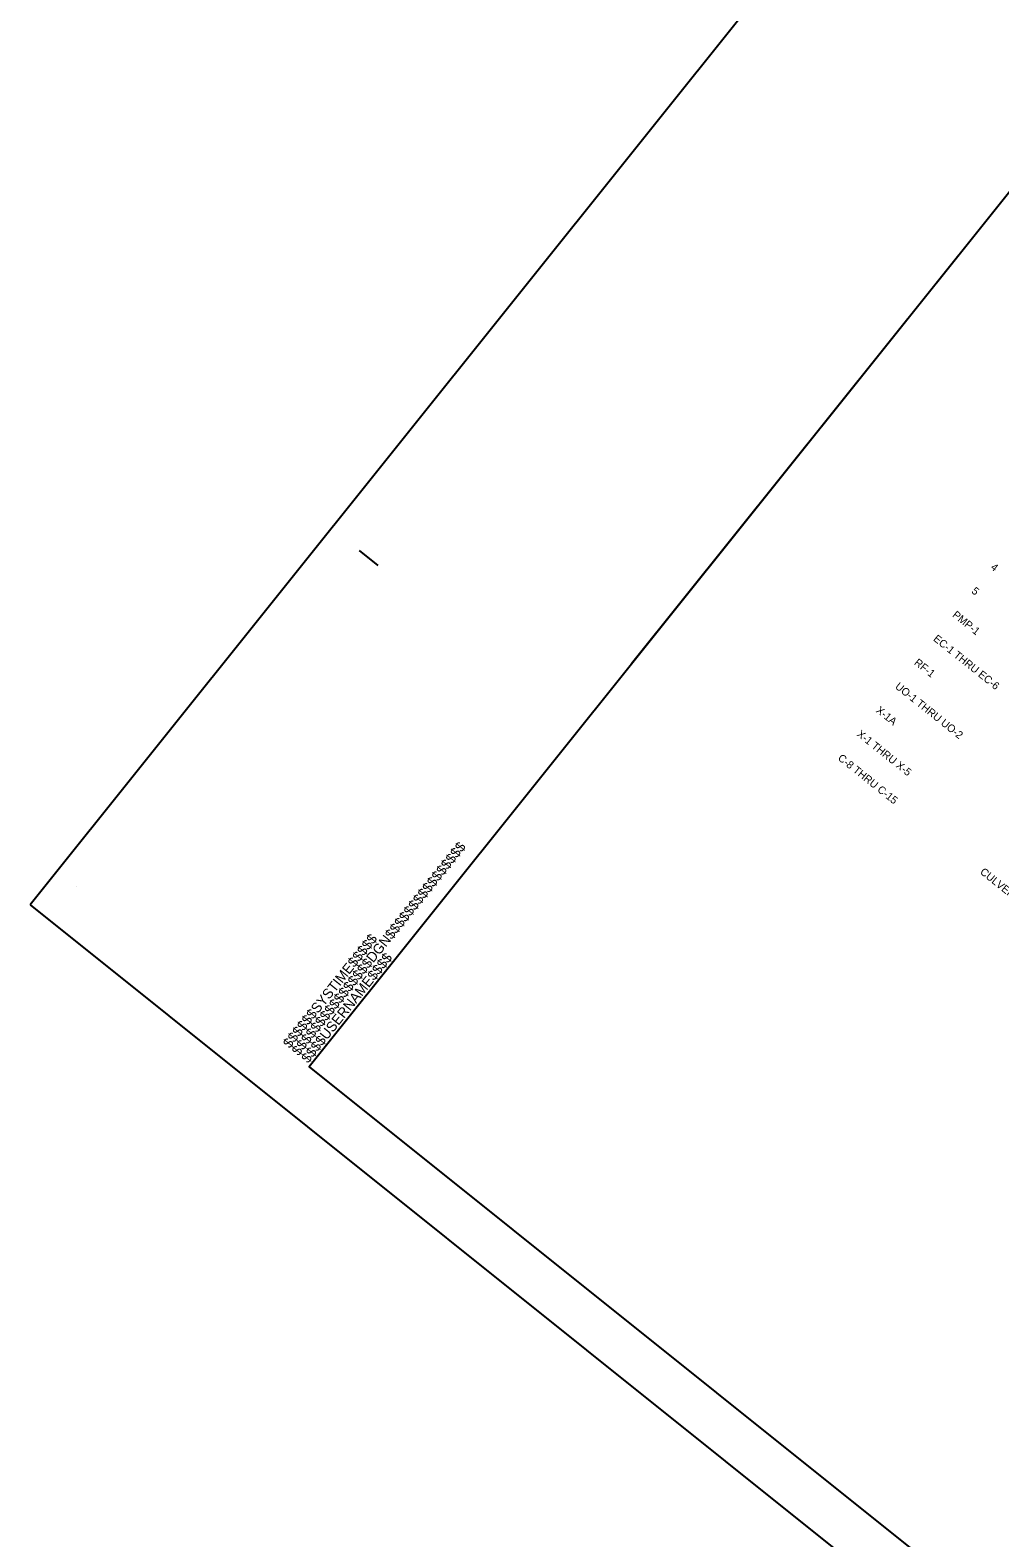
# Model space of a CAD drawing. Extents: x 1730256 to 1738218, y 910410 to 917906.
# Drawn here: x 1730256 to 1730764, y 911131 to 911921 of the extents above; entities that cross this region are included whole.
import ezdxf

# ---------------------------------------------------------------- set-up
doc = ezdxf.new("R2010")
doc.units = 0
for name, color, linetype in [('Old_Level_1', 7, 'Continuous'), ('Old_Level_18', 7, 'Continuous'), ('Old_Level_40', 7, 'Continuous'), ('Old_Level_41', 7, 'Continuous'), ('Old_Level_50', 7, 'Continuous'), ('Old_Level_51', 7, 'Continuous'), ('Old_Level_52', 7, 'Continuous')]:
    doc.layers.add(name, color=color, linetype=linetype)

msp = doc.modelspace()

# ---------------------------------------------------------------- linework, layer by layer
at = {"layer": 'Old_Level_1'}
msp.add_line((1731058.58, 912197.51), (1730571.35, 911588.71), dxfattribs=at)
at = {"layer": 'Old_Level_18'}
msp.add_line((1730402.49, 911377.72), (1730402.49, 911377.72), dxfattribs=at)
msp.add_lwpolyline([(1732229.7, 911260.24), (1731058.58, 912197.51), (1730402.49, 911377.72), (1731573.62, 910440.45)], close=True, dxfattribs=at)
at = {"layer": 'Old_Level_40'}
msp.add_line((1730402.49, 911377.72), (1730402.49, 911377.72), dxfattribs=at)
msp.add_line((1730402.49, 911377.72), (1730402.49, 911377.72), dxfattribs=at)
msp.add_line((1730402.49, 911377.72), (1730402.49, 911377.72), dxfattribs=at)
msp.add_line((1730402.49, 911377.72), (1730402.49, 911377.72), dxfattribs=at)
at = {"layer": 'Old_Level_41'}
msp.add_line((1730428.7, 911648.13), (1730438.46, 911640.32), dxfattribs=at)
msp.add_lwpolyline([(1730509.85, 911291.8), (1730509.85, 911291.8)], dxfattribs=at)
at = {"layer": 'Old_Level_50'}
msp.add_line((1730256.49, 911462.55), (1730256.49, 911462.55), dxfattribs=at)
at = {"layer": 'Old_Level_51'}
for p, q in [((1730943.82, 912321.37), (1730256.49, 911462.55)), ((1730256.49, 911462.55), (1731571.27, 910410.31))]:
    msp.add_line(p, q, dxfattribs=at)
at = {"layer": 'Old_Level_52'}
msp.add_line((1730280.66, 911471.96), (1730280.66, 911471.96), dxfattribs=at)

# ---------------------------------------------------------------- texts
at = {"layer": 'Old_Level_1'}
for s, height, p in [('4', 4, (1730758.97, 911638.74)), ('5', 4, (1730748.97, 911626.24)), ('PMP-1', 4, (1730738.97, 911613.75)), ('EC-1 THRU EC-6', 3.9999, (1730728.98, 911601.26)), ('RF-1', 4, (1730718.98, 911588.77)), ('UO-1 THRU UO-2', 3.9999, (1730708.98, 911576.28)), ('X-1A', 4, (1730698.98, 911563.78)), ('X-1 THRU X-5', 3.9999, (1730688.98, 911551.29)), ('C-8 THRU C-15', 3.9999, (1730678.99, 911538.8)), ('CULVERT PLANS', 3.9999, (1730753.44, 911479.21))]:
    msp.add_text(s, height=height, rotation=321.32919, dxfattribs=at).set_placement(p)
at = {"layer": 'Old_Level_41'}
for s, p in [('$$$$$$$$$$$$$$$$DGN$$$$$$$$$$$$$$$$', (1730397.05, 911383.16)), ('$$$$$$SYSTIME$$$$$', (1730392.45, 911387.1)), ('$$$$USERNAME$$$$', (1730402.03, 911379.31))]:
    msp.add_text(s, height=5.25, rotation=51.32919, dxfattribs=at).set_placement(p)

doc.saveas('drawing.dxf')
